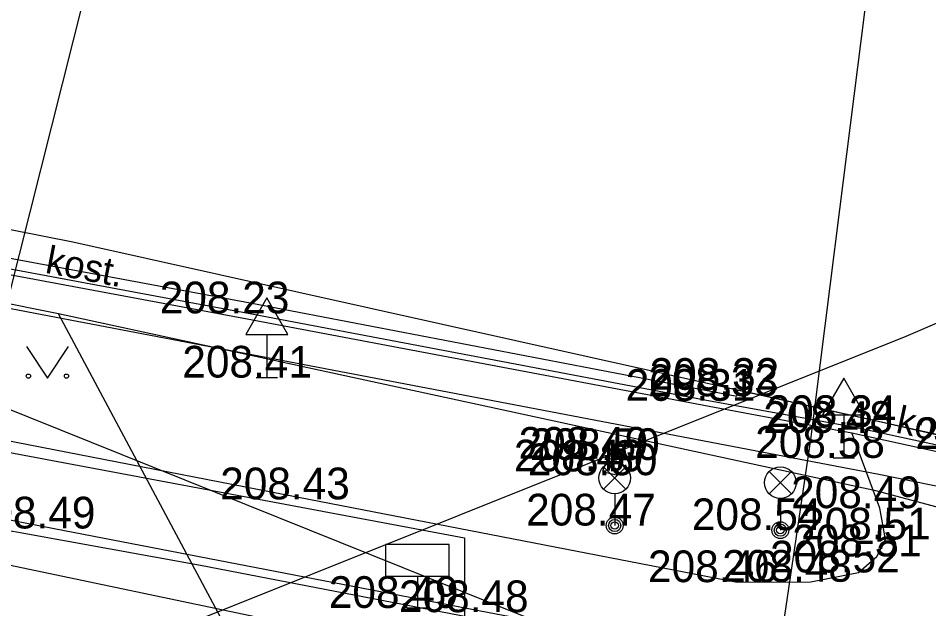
# Model space of a CAD drawing. Extents: x -524633 to -524336, y -1187893 to -1187683.
# Drawn here: x -524519.98 to -524498.44, y -1187743.78 to -1187729.81 of the extents above; entities that cross this region are included whole.
import ezdxf

# ---------------------------------------------------------------- set-up
doc = ezdxf.new("R2010")
doc.units = 0
for name, color, linetype in [('Hranice parcel', 7, 'Continuous'), ('Vrstva 1', 7, 'Continuous'), ('Vrstva 10', 7, 'Continuous'), ('Vrstva 11', 7, 'Continuous'), ('Vrstva 21', 7, 'Continuous'), ('Vrstva 3', 7, 'Continuous'), ('Vrstva 33', 7, 'Continuous'), ('Vrstva 34', 7, 'Continuous'), ('Vrstva 36', 7, 'Continuous'), ('Vrstva 4', 7, 'Continuous'), ('Vrstva 40', 7, 'Continuous'), ('Vrstva 52', 7, 'Continuous'), ('Vrstva 53', 7, 'Continuous'), ('Vrstva 54', 7, 'Continuous'), ('Vrstva 55', 7, 'Continuous')]:
    doc.layers.add(name, color=color, linetype=linetype)

msp = doc.modelspace()

# ---------------------------------------------------------------- linework, layer by layer
at = {"layer": 'Hranice parcel'}
for points in [[(-524573.93, -1187724.17), (-524518.69, -1187735.1), (-524499.46, -1187739.38)], [(-524519.03, -1187736.8), (-524523.94, -1187735.82), (-524529.6, -1187734.7)], [(-524509.72, -1187754.22), (-524515.56, -1187743.3), (-524519.03, -1187736.8)], [(-524488.795, -1187743.895), (-524499.69, -1187740.99), (-524519.03, -1187736.8)], [(-524499.46, -1187739.38), (-524489.297, -1187741.727)]]:
    msp.add_lwpolyline(points, dxfattribs=at)
at = {"layer": 'Vrstva 1'}
for p, q in [((-524514.54, -1187736.79), (-524514.54, -1187736.79)), ((-524514.1, -1187738.31), (-524514.1, -1187738.31)), ((-524502.98, -1187738.75), (-524502.98, -1187738.75)), ((-524502.95, -1187738.6), (-524502.95, -1187738.6)), ((-524503.61, -1187738.86), (-524503.61, -1187738.86)), ((-524500.26, -1187739.62), (-524500.26, -1187739.62)), ((-524500.18, -1187739.48), (-524500.18, -1187739.48)), ((-524506.05, -1187740.23), (-524506.05, -1187740.23)), ((-524505.75, -1187740.26), (-524505.75, -1187740.26)), ((-524500.45, -1187740.21), (-524500.45, -1187740.21)), ((-524506.16, -1187740.53), (-524506.16, -1187740.53)), ((-524505.8, -1187740.62), (-524505.8, -1187740.62)), ((-524513.11, -1187741.19), (-524513.11, -1187741.19)), ((-524499.6, -1187741.4), (-524499.6, -1187741.4)), ((-524519.13, -1187741.88), (-524519.13, -1187741.88)), ((-524505.87, -1187741.81), (-524505.87, -1187741.81)), ((-524501.95, -1187741.92), (-524501.95, -1187741.92)), ((-524499.46, -1187742.14), (-524499.46, -1187742.14)), ((-524499.67, -1187742.54), (-524499.67, -1187742.54)), ((-524500.1, -1187742.92), (-524500.1, -1187742.92)), ((-524502.97, -1187743.15), (-524502.97, -1187743.15)), ((-524501.23, -1187743.14), (-524501.23, -1187743.14)), ((-524510.54, -1187743.76), (-524510.54, -1187743.76))]:
    msp.add_line(p, q, dxfattribs=at)
at = {"layer": 'Vrstva 10'}
msp.add_lwpolyline([(-524568.939, -1187726.44), (-524568.55, -1187726.47), (-524556.49, -1187728.78), (-524544.45, -1187731.12), (-524530.269, -1187733.86), (-524524.26, -1187734.99), (-524524.27, -1187735.17), (-524524.19, -1187735.27), (-524524.04, -1187735.16), (-524523.98, -1187735.03), (-524514.54, -1187736.79), (-524503.61, -1187738.86), (-524500.18, -1187739.48), (-524495.139, -1187740.57), (-524489.47, -1187741.84)], dxfattribs=at)
at = {"layer": 'Vrstva 11'}
for points in [[(-524568.929, -1187726.18), (-524568.43, -1187726.15), (-524556.4, -1187728.45), (-524544.402, -1187730.875), (-524530.223, -1187733.614), (-524514.494, -1187736.544), (-524502.98, -1187738.75), (-524502.949, -1187738.6), (-524496.659, -1187740), (-524489.369, -1187741.66)], [(-524568.949, -1187726.57), (-524568.567, -1187726.599), (-524556.515, -1187728.908), (-524544.475, -1187731.248), (-524530.293, -1187733.988), (-524524.39, -1187735.1), (-524524.34, -1187735.33), (-524524.219, -1187735.389), (-524524.11, -1187735.39), (-524523.92, -1187735.18), (-524514.564, -1187736.918), (-524503.634, -1187738.988), (-524500.26, -1187739.62), (-524495.25, -1187740.71), (-524489.495, -1187741.999)], [(-524573.97, -1187728.18), (-524571.47, -1187728.67), (-524569.629, -1187730.26), (-524565.82, -1187730.99), (-524554.409, -1187733.18), (-524542.79, -1187735.45), (-524533.969, -1187737.14), (-524523.68, -1187739.13), (-524513.109, -1187741.19), (-524502.97, -1187743.15), (-524501.229, -1187743.14), (-524500.099, -1187742.92), (-524499.67, -1187742.54), (-524499.46, -1187742.14), (-524499.599, -1187741.4), (-524500.26, -1187739.62)], [(-524576.43, -1187730.76), (-524566.63, -1187732.68), (-524553.039, -1187735.29), (-524544.049, -1187737.05), (-524531.749, -1187739.42), (-524519.129, -1187741.88), (-524508.88, -1187743.86), (-524502.049, -1187745.16)], [(-524505.75, -1187740.26), (-524506.049, -1187740.23), (-524506.159, -1187740.53), (-524505.8, -1187740.62)], [(-524505.8, -1187740.62), (-524505.75, -1187740.26)]]:
    msp.add_lwpolyline(points, dxfattribs=at)
at = {"layer": 'Vrstva 21'}
msp.add_lwpolyline([(-524525.529, -1187744.82), (-524525.469, -1187742.71), (-524523.219, -1187742.11), (-524511.34, -1187744.6), (-524505.6, -1187745.76), (-524504.909, -1187747.34)], dxfattribs=at)
at = {"layer": 'Vrstva 33'}
for p, q in [((-524506.135, -1187740.95), (-524505.605, -1187740.42)), ((-524506.135, -1187740.42), (-524505.605, -1187740.95)), ((-524502.215, -1187741.06), (-524501.685, -1187740.53)), ((-524502.215, -1187740.53), (-524501.685, -1187741.06)), ((-524505.87, -1187741.06), (-524505.87, -1187741.81)), ((-524501.95, -1187741.17), (-524501.95, -1187741.92))]:
    msp.add_line(p, q, dxfattribs=at)
for centre, radius in [((-524505.87, -1187740.685), 0.375), ((-524501.95, -1187740.795), 0.375), ((-524505.87, -1187741.81), 0.2), ((-524505.87, -1187741.81), 0.145), ((-524505.87, -1187741.81), 0.0876), ((-524501.95, -1187741.92), 0.2), ((-524501.95, -1187741.92), 0.145), ((-524501.95, -1187741.92), 0.0876)]:
    msp.add_circle(centre, radius, dxfattribs=at)
at = {"layer": 'Vrstva 34'}
for p, q in [((-524514.1, -1187737.292), (-524514.1, -1187738.31)), ((-524514.35, -1187738.31), (-524513.85, -1187738.31)), ((-524500.449, -1187739.192), (-524500.449, -1187740.21)), ((-524500.699, -1187740.21), (-524500.199, -1187740.21)), ((-524510.539, -1187743.01), (-524510.539, -1187743.76)), ((-524510.789, -1187743.76), (-524510.289, -1187743.76))]:
    msp.add_line(p, q, dxfattribs=at)
for points in [[(-524514.6, -1187737.292), (-524513.6, -1187737.292), (-524514.1, -1187736.426)], [(-524500.949, -1187739.192), (-524499.949, -1187739.192), (-524500.449, -1187738.326)], [(-524511.289, -1187743.01), (-524509.789, -1187743.01), (-524509.789, -1187742.26), (-524511.289, -1187742.26)]]:
    msp.add_lwpolyline(points, close=True, dxfattribs=at)
at = {"layer": 'Vrstva 36'}
msp.add_lwpolyline([(-524519.79, -1187737.576), (-524519.29, -1187738.326), (-524518.79, -1187737.576)], dxfattribs=at)
for centre in [(-524519.741, -1187738.276), (-524518.841, -1187738.276)]:
    msp.add_circle(centre, 0.05, dxfattribs=at)
at = {"layer": 'Vrstva 52'}
for p, q in [((-524550.502, -1187734.408), (-524509.425, -1187742.101)), ((-524509.425, -1187742.101), (-524509.425, -1187745.673))]:
    msp.add_line(p, q, dxfattribs=at)
at = {"layer": 'Vrstva 53'}
msp.add_line((-524531.071, -1187734.69), (-524502.2, -1187746.29), dxfattribs=at)
for points in [[(-524499.468, -1187725.8), (-524499.705, -1187727.675), (-524499.956, -1187729.659), (-524500.547, -1187734.331), (-524501.236, -1187739.779), (-524502.2, -1187746.29)], [(-524502.2, -1187746.29), (-524503.62, -1187745.08), (-524515.67, -1187742.76), (-524524.47, -1187741.16), (-524525.62, -1187746.23)]]:
    msp.add_lwpolyline(points, dxfattribs=at)
at = {"layer": 'Vrstva 54'}
msp.add_lwpolyline([(-524489.058, -1187742.759), (-524499.62, -1187740.6), (-524570.13, -1187727.14), (-524573.74, -1187725.2), (-524583.929, -1187713.264)], dxfattribs=at)
at = {"layer": 'Vrstva 55'}
msp.add_line((-524516.896, -1187723.213), (-524522.885, -1187746.999), dxfattribs=at)
msp.add_lwpolyline([(-524537.22, -1187752.94), (-524523.66, -1187747.21), (-524498.97, -1187737.33), (-524491.101, -1187733.95)], dxfattribs=at)

# ---------------------------------------------------------------- texts
at = {"layer": 'Vrstva 3'}
for s, p in [('208.23', (-524516.634, -1187736.79)), ('208.41', (-524516.1, -1187738.31)), ('208.31', (-524505.61, -1187738.86)), ('208.49', (-524508.144, -1187740.23)), ('208.58', (-524502.544, -1187740.21)), ('208.43', (-524515.204, -1187741.19)), ('208.49', (-524501.694, -1187741.4)), ('208.47', (-524507.964, -1187741.81)), ('208.48', (-524503.324, -1187743.14)), ('208.49', (-524512.634, -1187743.76))]:
    msp.add_text(s, height=0.75, dxfattribs=at).set_placement(p)
at = {"layer": 'Vrstva 4'}
for s, p in [('208.32', (-524505.044, -1187738.6)), ('208.33', (-524505.074, -1187738.75)), ('208.34', (-524502.274, -1187739.48)), ('208.48', (-524502.354, -1187739.62)), ('208.42', (-524498.754, -1187740)), ('208.50', (-524507.874, -1187740.26)), ('208.49', (-524508.254, -1187740.53)), ('208.50', (-524507.924, -1187740.62)), ('208.49', (-524521.224, -1187741.88)), ('208.54', (-524504.044, -1187741.92)), ('208.51', (-524501.46, -1187742.14)), ('208.51', (-524501.67, -1187742.54)), ('208.52', (-524502.194, -1187742.92)), ('208.46', (-524505.081, -1187743.15)), ('208.48', (-524510.974, -1187743.86))]:
    msp.add_text(s, height=0.75, dxfattribs=at).set_placement(p)
at = {"layer": 'Vrstva 40'}
for rotation, p in [(349.1568, (-524519.366, -1187735.828)), (347.7983, (-524499.242, -1187739.608))]:
    msp.add_text('kost.', height=0.65, rotation=rotation, dxfattribs=at).set_placement(p)
msp.add_text('b.', height=0.65, dxfattribs=at).set_placement((-524506.109, -1187740.509))

doc.saveas('drawing.dxf')
